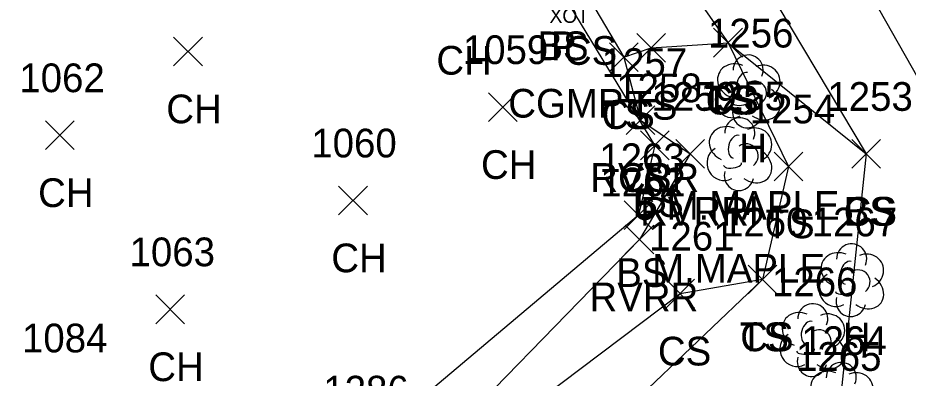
# Model space of a CAD drawing. Extents: x 1469310 to 1475157, y 493997 to 498873.
# Drawn here: x 1469498.4 to 1469560.4, y 498537.1 to 498562.2 of the extents above; entities that cross this region are included whole.
import ezdxf

# ---------------------------------------------------------------- set-up
doc = ezdxf.new("R2010")
doc.units = 0
for name, color, linetype in [('B_A', 7, 'Continuous'), ('D_A', 7, 'Continuous'), ('D_C', 7, 'Continuous'), ('L_A', 7, 'Continuous'), ('L_C', 7, 'Continuous'), ('L_I', 7, 'Continuous'), ('L_TIC', 7, 'Continuous'), ('LAWE', 7, 'Continuous'), ('LELB', 7, 'Continuous'), ('LTD', 7, 'Continuous')]:
    doc.layers.add(name, color=color, linetype=linetype)

msp = doc.modelspace()

# ---------------------------------------------------------------- linework, layer by layer
at = {"layer": 'L_TIC'}
for points in [[(1469541.482, 498559.056), (1469543.482, 498561.056)], [(1469543.482, 498559.056), (1469541.482, 498561.056)], [(1469546.828, 498559.419), (1469548.828, 498561.419)], [(1469548.828, 498559.419), (1469546.828, 498561.419)], [(1469546.828, 498559.419), (1469548.828, 498561.419)], [(1469548.828, 498559.419), (1469546.828, 498561.419)], [(1469509.23, 498558.805), (1469511.23, 498560.805)], [(1469511.23, 498558.805), (1469509.23, 498560.805)], [(1469539.583, 498558.415), (1469541.583, 498560.415)], [(1469541.583, 498558.415), (1469539.583, 498560.415)], [(1469539.583, 498558.415), (1469541.583, 498560.415)], [(1469541.583, 498558.415), (1469539.583, 498560.415)], [(1469531.143, 498554.929), (1469533.143, 498556.929)], [(1469533.143, 498554.929), (1469531.143, 498556.929)], [(1469540.729, 498554.03), (1469542.729, 498556.03)], [(1469542.729, 498554.03), (1469540.729, 498556.03)], [(1469540.729, 498554.03), (1469542.729, 498556.03)], [(1469542.729, 498554.03), (1469540.729, 498556.03)], [(1469500.304, 498552.972), (1469502.304, 498554.972)], [(1469502.304, 498552.972), (1469500.304, 498554.972)], [(1469541.737, 498552.271), (1469543.737, 498554.271)], [(1469543.737, 498552.271), (1469541.737, 498554.271)], [(1469544.194, 498551.674), (1469546.194, 498553.674)], [(1469546.194, 498551.674), (1469544.194, 498553.674)], [(1469556.439, 498551.672), (1469558.439, 498553.672)], [(1469558.439, 498551.672), (1469556.439, 498553.672)], [(1469556.439, 498551.672), (1469558.439, 498553.672)], [(1469558.439, 498551.672), (1469556.439, 498553.672)], [(1469551.035, 498550.8), (1469553.035, 498552.8)], [(1469553.035, 498550.8), (1469551.035, 498552.8)], [(1469520.72, 498548.428), (1469522.72, 498550.428)], [(1469522.72, 498548.428), (1469520.72, 498550.428)], [(1469540.606, 498547.405), (1469542.606, 498549.405)], [(1469542.606, 498547.405), (1469540.606, 498549.405)], [(1469540.673, 498545.713), (1469542.673, 498547.713)], [(1469542.673, 498545.713), (1469540.673, 498547.713)], [(1469549.238, 498542.932), (1469551.238, 498544.932)], [(1469551.238, 498542.932), (1469549.238, 498544.932)], [(1469549.238, 498542.932), (1469551.238, 498544.932)], [(1469551.238, 498542.932), (1469549.238, 498544.932)], [(1469543.507, 498541.938), (1469545.507, 498543.938)], [(1469545.507, 498541.938), (1469543.507, 498543.938)], [(1469507.979, 498540.848), (1469509.979, 498542.848)], [(1469509.979, 498540.848), (1469507.979, 498542.848)]]:
    msp.add_lwpolyline(points, dxfattribs=at)
at = {"layer": 'LAWE'}
msp.add_lwpolyline([(1469541.729, 498555.03), (1469545.194, 498552.674), (1469541.673, 498546.713), (1469525.678, 498530.281), (1469522.399, 498516.014), (1469543.45, 498481.784), (1469558.176, 498452.243), (1469573.197, 498427.492), (1469574.965, 498400.532), (1469574.711, 498375.537), (1469575.481, 498352.314), (1469575.939, 498330.627)], dxfattribs=at)
at = {"layer": 'LELB'}
for points in [[(1469413.419, 498730.944), (1469442.517, 498698.703), (1469468.453, 498674.773), (1469500.535, 498635.821), (1469519.003, 498614.534), (1469533.172, 498594.862), (1469544.52, 498587.119), (1469562.893, 498554.703), (1469567.788, 498543.524), (1469559.261, 498528.602), (1469545.395, 498521.66), (1469536.791, 498513.026)], [(1469434.428, 498661.856), (1469439.868, 498652.509), (1469461.918, 498616.733), (1469481.608, 498592.394), (1469486.836, 498579.655), (1469494.023, 498578.216), (1469506.126, 498583.816), (1469519.691, 498588.789), (1469534.493, 498586.197), (1469541.719, 498579.078), (1469557.439, 498552.672)], [(1469428.533, 498658.897), (1469433.568, 498648.515), (1469459.288, 498614.436), (1469478.332, 498589.059), (1469483.968, 498576.627), (1469489.341, 498572.759), (1469492.494, 498571.977), (1469507.99, 498581.091), (1469520.418, 498585.286), (1469534.627, 498584.287), (1469538.322, 498574.02), (1469547.828, 498560.419), (1469557.439, 498552.672), (1469555.667, 498535.666), (1469539.848, 498524.73), (1469536.791, 498513.026), (1469549.045, 498482.48), (1469564.461, 498458.053), (1469576.503, 498438.755), (1469578.882, 498431.595)], [(1469530.314, 498572.636), (1469535.638, 498568.508), (1469537.962, 498563.876), (1469540.583, 498559.415), (1469541.729, 498555.03)], [(1469542.737, 498553.271), (1469536.113, 498564.2)], [(1469540.583, 498559.415), (1469542.482, 498560.056), (1469547.828, 498560.419), (1469552.035, 498551.8), (1469550.238, 498543.932), (1469532.312, 498526.834), (1469530.23, 498517.663), (1469549.045, 498482.48)], [(1469542.737, 498553.271), (1469541.606, 498548.405), (1469522.397, 498532.218), (1469522.156, 498514.949), (1469541.186, 498477.775), (1469556.439, 498450.638), (1469569.238, 498427.493), (1469571.751, 498396.282), (1469571.573, 498374.721), (1469573.653, 498352.837), (1469573.817, 498331.47)], [(1469550.238, 498543.932), (1469544.507, 498542.938), (1469527.965, 498530.455), (1469525.182, 498518.628), (1469546.359, 498481.192), (1469563.05, 498455.924), (1469576.503, 498438.755)]]:
    msp.add_lwpolyline(points, dxfattribs=at)
at = {"layer": 'LTD'}
for p, q in [((1469549.183, 498557.082), (1469549.183, 498557.082)), ((1469549.183, 498557.082), (1469549.183, 498557.082)), ((1469548.605, 498552.708), (1469548.605, 498552.708)), ((1469548.605, 498552.708), (1469548.605, 498552.708)), ((1469556.393, 498543.929), (1469556.393, 498543.929)), ((1469556.393, 498543.929), (1469556.393, 498543.929)), ((1469553.685, 498539.759), (1469553.685, 498539.759)), ((1469553.685, 498539.759), (1469553.685, 498539.759))]:
    msp.add_line(p, q, dxfattribs=at)
for centre in [(1469549.23, 498558.516), (1469548.652, 498554.142), (1469556.44, 498545.363), (1469553.732, 498541.193), (1469555.714, 498537.1)]:
    msp.add_arc(centre, 1.047, 335.52715, 180.95627, dxfattribs=at)
for centre, major_axis, ratio, start_param, end_param in [((1469548.391, 498557.749), (1.21, -0.512), 0.895232, 1.570796, 4.712389), ((1469550.225, 498557.666), (-1.141, -0.483), 0.949671, 1.570796, 4.712389), ((1469548.975, 498557.541), (-0.208, -0.792), 0.645439, 3.141593, 6.283185), ((1469549.683, 498556.916), (-0.5, 0.667), 0.989748, 3.141593, 6.283185), ((1469548.1, 498556.374), (0.584, -1.042), 0.959034, 3.141593, 6.283185), ((1469550.183, 498556.249), (-1.09, 0.792), 0.841452, 1.570796, 4.712389), ((1469548.725, 498556.332), (-0.625, -0.083), 0.423636, 0, 3.141593), ((1469549.183, 498555.582), (0.265, 1.061), 0.942809, 1.570796, 4.712389), ((1469547.813, 498553.375), (1.21, -0.512), 0.895232, 1.570796, 4.712389), ((1469549.647, 498553.292), (-1.141, -0.483), 0.949671, 1.570796, 4.712389), ((1469548.397, 498553.167), (-0.208, -0.792), 0.645439, 3.141593, 6.283185), ((1469549.105, 498552.542), (-0.5, 0.667), 0.989748, 3.141593, 6.283185), ((1469547.522, 498552), (0.584, -1.042), 0.959034, 3.141593, 6.283185), ((1469549.605, 498551.875), (-1.09, 0.792), 0.841452, 1.570796, 4.712389), ((1469548.147, 498551.958), (-0.625, -0.083), 0.423636, 0, 3.141593), ((1469548.605, 498551.208), (0.265, 1.061), 0.942809, 1.570796, 4.712389), ((1469555.601, 498544.596), (1.21, -0.512), 0.895232, 1.570796, 4.712389), ((1469557.435, 498544.513), (-1.141, -0.483), 0.949671, 1.570796, 4.712389), ((1469556.185, 498544.388), (-0.208, -0.792), 0.645439, 3.141593, 6.283185), ((1469555.31, 498543.221), (0.584, -1.042), 0.959034, 3.141593, 6.283185), ((1469556.893, 498543.763), (-0.5, 0.667), 0.989748, 3.141593, 6.283185), ((1469557.393, 498543.096), (-1.09, 0.792), 0.841452, 1.570796, 4.712389), ((1469555.935, 498543.179), (-0.625, -0.083), 0.423636, 0, 3.141593), ((1469556.393, 498542.429), (0.265, 1.061), 0.942809, 1.570796, 4.712389), ((1469552.893, 498540.426), (1.21, -0.512), 0.895232, 1.570796, 4.712389), ((1469554.726, 498540.343), (-1.141, -0.483), 0.949671, 1.570796, 4.712389), ((1469553.476, 498540.218), (-0.208, -0.792), 0.645439, 3.141593, 6.283185), ((1469554.185, 498539.593), (-0.5, 0.667), 0.989748, 3.141593, 6.283185), ((1469552.602, 498539.051), (0.584, -1.042), 0.959034, 3.141593, 6.283185), ((1469554.685, 498538.926), (-1.09, 0.792), 0.841452, 1.570796, 4.712389), ((1469553.227, 498539.009), (-0.625, -0.083), 0.423636, 0, 3.141593), ((1469553.685, 498538.259), (0.265, 1.061), 0.942809, 1.570796, 4.712389), ((1469554.875, 498536.333), (1.21, -0.512), 0.895232, 1.570796, 4.712389), ((1469556.709, 498536.25), (-1.141, -0.483), 0.949671, 1.570796, 4.712389)]:
    msp.add_ellipse(centre, major_axis=major_axis, ratio=ratio, start_param=start_param, end_param=end_param, dxfattribs=at)

# ---------------------------------------------------------------- texts
at = {"layer": 'B_A'}
msp.add_text('XOT', height=1, dxfattribs=at).set_placement((1469535.402, 498561.801))
at = {"layer": 'D_A'}
msp.add_text('P', height=2, dxfattribs=at).set_placement((1469535.491, 498559.2))
at = {"layer": 'D_C'}
msp.add_text('CGMP', height=2, dxfattribs=at).set_placement((1469532.53, 498555.2))
at = {"layer": 'L_A'}
for s, p in [('BS', (1469534.554, 498559.2)), ('CS', (1469536.403, 498558.876)), ('CH', (1469527.524, 498558.191)), ('TS', (1469546.238, 498555.419)), ('CS', (1469546.269, 498555.419)), ('CH', (1469508.718, 498554.805)), ('TS', (1469540.891, 498555.056)), ('TS', (1469538.993, 498554.415)), ('CS', (1469539.024, 498554.415)), ('H', (1469548.616, 498552.082)), ('CH', (1469530.631, 498550.929)), ('RVRR', (1469538.241, 498550.03)), ('CS', (1469540.17, 498550.03)), ('CH', (1469499.792, 498548.972)), ('BS', (1469541.178, 498548.271)), ('H', (1469548.038, 498547.708)), ('CS', (1469555.88, 498547.672)), ('BS', (1469555.88, 498547.672)), ('RVRR', (1469541.706, 498547.674)), ('TS', (1469550.445, 498546.8)), ('CH', (1469520.208, 498544.428)), ('BS', (1469540.047, 498543.405)), ('RVRR', (1469538.185, 498541.713)), ('TS', (1469548.648, 498538.932)), ('CS', (1469548.679, 498538.932)), ('H', (1469555.826, 498538.929)), ('CS', (1469542.948, 498537.938)), ('CH', (1469507.467, 498536.848))]:
    msp.add_text(s, height=2, dxfattribs=at).set_placement(p)
at = {"layer": 'L_C'}
for s, p in [('5 M.MAPLE', (1469541.325, 498548.082)), ('M.MAPLE', (1469542.542, 498543.708))]:
    msp.add_text(s, height=2, dxfattribs=at).set_placement(p)
at = {"layer": 'L_I'}
for s, p in [('1256', (1469546.435, 498560.082)), ('1059', (1469529.364, 498558.929)), ('1257', (1469539.036, 498558.03)), ('1257', (1469539.036, 498558.03)), ('1062', (1469498.486, 498556.972)), ('1258', (1469540.044, 498556.271)), ('1259', (1469542.493, 498555.674)), ('1255', (1469545.912, 498555.708)), ('1253', (1469554.746, 498555.672)), ('1253', (1469554.746, 498555.672)), ('1254', (1469549.343, 498554.8)), ('1060', (1469518.815, 498552.428)), ('1263', (1469538.866, 498551.405)), ('1262', (1469538.933, 498549.713)), ('1260', (1469547.412, 498546.932)), ('1260', (1469547.412, 498546.932)), ('1267', (1469553.653, 498546.929)), ('1261', (1469542.334, 498545.938)), ('1063', (1469506.16, 498544.848)), ('1266', (1469550.89, 498542.759)), ('1084', (1469498.672, 498538.85)), ('1264', (1469552.927, 498538.666)), ('1264', (1469552.927, 498538.666)), ('1265', (1469552.565, 498537.562)), ('1286', (1469519.649, 498535.218))]:
    msp.add_text(s, height=2, dxfattribs=at).set_placement(p)

doc.saveas('drawing.dxf')
